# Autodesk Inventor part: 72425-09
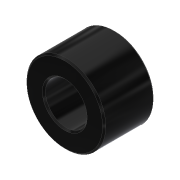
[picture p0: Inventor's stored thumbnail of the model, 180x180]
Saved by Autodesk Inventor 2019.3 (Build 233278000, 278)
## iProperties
Created: 2013-06
Part Number: 72425-09
Material: Ogólny
Document SubType Name: Modeling
Designer: CADENGINEERING4
Density: 1 g/cm^3
Appearance: Gładki — czarny
Author: CADENGINEERING4
Revision Number: ÈÎºÎ
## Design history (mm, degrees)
feature "ÊäÈë1"
node "Bryła1"
